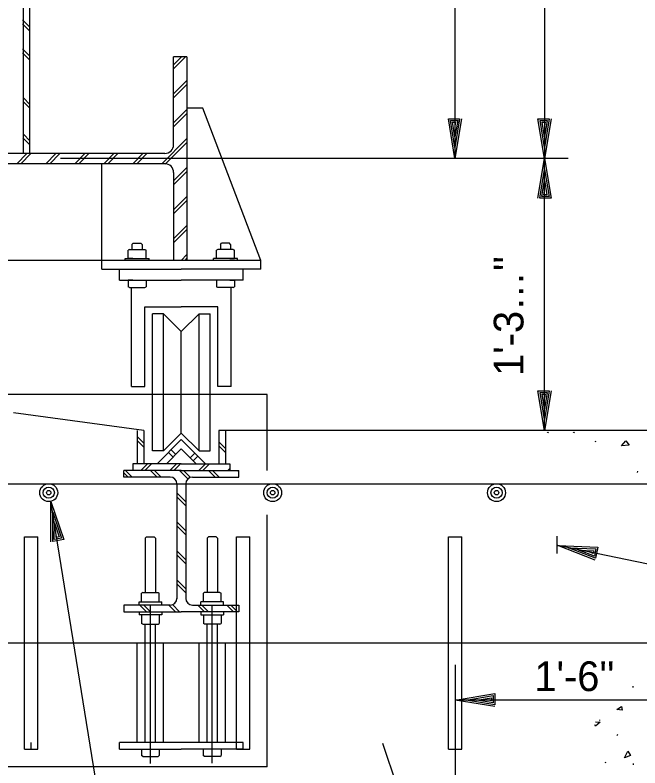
# Model space of a CAD drawing. Extents: x 0 to 320, y -4 to 473.
# Drawn here: x 29.538 to 32.485, y 15.085 to 18.631 of the extents above; entities that cross this region are included whole.
import ezdxf

# ---------------------------------------------------------------- set-up
doc = ezdxf.new("R2010")
doc.units = 0
for name, color, linetype in [('Level 10', 7, 'Continuous'), ('Level 2', 7, 'Continuous'), ('Level 25', 7, 'Continuous'), ('Level 3', 7, 'Continuous'), ('Level 44', 7, 'Continuous'), ('Level 50', 7, 'Continuous')]:
    doc.layers.add(name, color=color, linetype=linetype)

msp = doc.modelspace()

# ---------------------------------------------------------------- linework, layer by layer
at = {"layer": 'Level 10'}
for p, q in [((32.2744, 16.6204), (32.2772, 16.6259)), ((32.4725, 16.4769), (32.4743, 16.4832)), ((32.4522, 15.4636), (32.4522, 15.4694)), ((32.2959, 15.3076), (32.2955, 15.3122)), ((32.3775, 15.2381), (32.3803, 15.2436)), ((32.323, 15.107), (32.3222, 15.1117)), ((32.4544, 15.0996), (32.4544, 15.1059))]:
    msp.add_line(p, q, dxfattribs=at)
for points in [[(32.0532, 16.6662), (32.05, 16.6634), (32.0485, 16.6662)], [(32.1753, 16.6662), (32.1722, 16.6634), (32.1707, 16.6662)], [(32.2975, 15.3009), (32.2753, 15.2811), (32.2718, 15.2876)], [(32.2744, 15.3025), (32.2975, 15.3009)]]:
    msp.add_lwpolyline(points, dxfattribs=at)
for points in [[(32.3972, 16.6016), (32.4178, 16.6254), (32.4344, 16.6057)], [(32.4009, 15.3566), (32.3756, 15.3598), (32.3969, 15.3741)], [(32.4408, 15.1434), (32.4124, 15.1323), (32.4274, 15.1631)]]:
    msp.add_lwpolyline(points, close=True, dxfattribs=at)
at = {"layer": 'Level 2'}
for p, q in [((29.5776, 17.979), (29.5776, 22.1736)), ((29.6089, 17.979), (29.6089, 21.6319)), ((29.6053, 18.5767), (29.5741, 18.608)), ((29.6053, 18.5579), (29.5741, 18.5891)), ((29.6053, 18.44), (29.5741, 18.4713)), ((29.6053, 18.4212), (29.5741, 18.4524)), ((30.286, 18.0207), (30.286, 18.434)), ((30.3485, 18.434), (30.286, 18.434)), ((30.286, 18.3781), (30.3418, 18.434)), ((30.286, 18.397), (30.323, 18.434)), ((30.3485, 18.434), (30.3485, 17.4757)), ((30.286, 18.2603), (30.3485, 18.3228)), ((30.286, 18.2414), (30.3485, 18.3039)), ((29.6089, 18.2097), (29.5776, 18.2409)), ((29.6076, 18.1921), (29.5776, 18.2221)), ((30.4235, 18.1921), (30.3485, 18.1921)), ((30.6974, 17.4757), (30.4235, 18.1921)), ((30.286, 18.1236), (30.3485, 18.1861)), ((30.286, 18.1047), (30.3485, 18.1672)), ((29.6064, 18.0218), (29.5752, 18.0531)), ((29.6089, 18.0384), (29.5776, 18.0696)), ((30.2298, 17.9307), (30.3485, 18.0494)), ((30.2465, 17.9285), (30.3485, 18.0305)), ((30.2443, 17.979), (29.1558, 17.979)), ((29.5462, 17.9307), (29.5946, 17.979)), ((29.5651, 17.9307), (29.6134, 17.979)), ((29.6829, 17.9307), (29.7313, 17.979)), ((29.7018, 17.9307), (29.7501, 17.979)), ((32.146, 17.9548), (29.7529, 17.9548)), ((29.8197, 17.9307), (29.868, 17.979)), ((29.8385, 17.9307), (29.8868, 17.979)), ((29.9564, 17.9307), (30.0047, 17.979)), ((29.9752, 17.9307), (30.0236, 17.979)), ((30.0931, 17.9307), (30.1414, 17.979)), ((30.1119, 17.9307), (30.1603, 17.979)), ((30.2443, 17.9307), (29.1558, 17.9307)), ((29.9474, 17.4757), (29.9474, 17.9307)), ((30.286, 17.8502), (30.3485, 17.9127)), ((30.286, 17.8313), (30.3485, 17.8938)), ((30.286, 17.889), (30.286, 17.4757)), ((30.286, 17.7135), (30.3485, 17.776)), ((30.286, 17.6946), (30.3485, 17.7571)), ((30.286, 17.5768), (30.3485, 17.6393)), ((30.286, 17.5579), (30.3485, 17.6204)), ((30.0898, 17.5508), (30.0959, 17.5569)), ((30.0959, 17.5569), (30.1323, 17.5569)), ((30.1383, 17.5508), (30.1323, 17.5569)), ((30.5065, 17.5508), (30.5126, 17.5569)), ((30.5489, 17.5569), (30.5126, 17.5569)), ((30.555, 17.5508), (30.5489, 17.5569)), ((30.0778, 17.5274), (30.0722, 17.5242)), ((30.0722, 17.4844), (30.0722, 17.5242)), ((30.0778, 17.5274), (30.1503, 17.5274)), ((30.0898, 17.5508), (30.0898, 17.5274)), ((30.1383, 17.5508), (30.1383, 17.5274)), ((30.1503, 17.5274), (30.1559, 17.5242)), ((30.1559, 17.4844), (30.1559, 17.5242)), ((30.4945, 17.5274), (30.4889, 17.5242)), ((30.4889, 17.4844), (30.4889, 17.5242)), ((30.567, 17.5274), (30.4945, 17.5274)), ((30.5065, 17.5508), (30.5065, 17.5274)), ((30.555, 17.5508), (30.555, 17.5274)), ((30.567, 17.5274), (30.5726, 17.5242)), ((30.5726, 17.4844), (30.5726, 17.5242)), ((30.0574, 17.4844), (30.1708, 17.4844)), ((30.0574, 17.4757), (30.0574, 17.4844)), ((30.0722, 17.4844), (30.1559, 17.4844)), ((30.0934, 17.4844), (30.0722, 17.4844)), ((30.0898, 17.4829), (30.0898, 17.4844)), ((30.1383, 17.4829), (30.1383, 17.4844)), ((30.1708, 17.4757), (30.1708, 17.4844)), ((30.3216, 17.4757), (30.3485, 17.5025)), ((30.3404, 17.4757), (30.3485, 17.4837)), ((30.5874, 17.4844), (30.4741, 17.4844)), ((30.4741, 17.4757), (30.4741, 17.4844)), ((30.5726, 17.4844), (30.4889, 17.4844)), ((30.5065, 17.4829), (30.5065, 17.4844)), ((30.5514, 17.4844), (30.5726, 17.4844)), ((30.555, 17.4829), (30.555, 17.4844)), ((30.5874, 17.4757), (30.5874, 17.4844)), ((30.6974, 17.4757), (28.7443, 17.4757)), ((29.9474, 17.434), (29.9474, 17.4757)), ((30.6974, 17.434), (30.6974, 17.4757)), ((29.9474, 17.434), (30.3224, 17.434)), ((30.0308, 17.3819), (30.0308, 17.434)), ((30.6974, 17.434), (30.3224, 17.434)), ((30.6141, 17.3819), (30.6141, 17.434)), ((30.0308, 17.3819), (30.3224, 17.3819)), ((30.0724, 17.3818), (30.1562, 17.3818)), ((30.0936, 17.3818), (30.0724, 17.3818)), ((30.0724, 17.3818), (30.0724, 17.3511)), ((30.0901, 17.3833), (30.0901, 17.3818)), ((30.1386, 17.3833), (30.1386, 17.3818)), ((30.1562, 17.3818), (30.1562, 17.3511)), ((30.6141, 17.3819), (30.3224, 17.3819)), ((30.5724, 17.3818), (30.4886, 17.3818)), ((30.4886, 17.3818), (30.4886, 17.3511)), ((30.5063, 17.3833), (30.5063, 17.3818)), ((30.5512, 17.3818), (30.5724, 17.3818)), ((30.5548, 17.3833), (30.5548, 17.3818)), ((30.5724, 17.3818), (30.5724, 17.3511)), ((30.0781, 17.3478), (30.0724, 17.3511)), ((30.0781, 17.3478), (30.1506, 17.3478)), ((30.0878, 16.8819), (30.0878, 17.3478)), ((30.1506, 17.3478), (30.1562, 17.3511)), ((30.4943, 17.3478), (30.4886, 17.3511)), ((30.5668, 17.3478), (30.4943, 17.3478)), ((30.5571, 16.8819), (30.5571, 17.3478)), ((30.5668, 17.3478), (30.5724, 17.3511)), ((30.1503, 16.8819), (30.1503, 17.2569)), ((30.1503, 17.2569), (30.3224, 17.2569)), ((30.4946, 17.2569), (30.3224, 17.2569)), ((30.4946, 16.8819), (30.4946, 17.2569)), ((30.187, 16.5781), (30.187, 17.2239)), ((30.2391, 17.2239), (30.187, 17.2239)), ((30.2391, 16.5781), (30.2391, 17.2239)), ((30.2391, 17.2239), (30.3224, 17.1406)), ((30.4058, 17.2239), (30.3224, 17.1406)), ((30.4058, 16.5781), (30.4058, 17.2239)), ((30.4058, 17.2239), (30.4578, 17.2239)), ((30.4578, 16.5781), (30.4578, 17.2239)), ((30.3224, 16.6614), (30.3224, 17.1406)), ((30.3224, 16.6614), (30.3224, 17.1406)), ((30.0878, 16.8819), (30.1503, 16.8819)), ((30.5571, 16.8819), (30.4946, 16.8819)), ((30.7278, 16.8433), (29.3706, 16.8433)), ((30.7278, 16.4866), (30.7278, 16.8433)), ((30.1453, 16.6736), (29.5308, 16.7569)), ((30.1141, 16.6736), (30.1141, 16.5173)), ((30.1453, 16.6736), (30.1453, 16.5173)), ((30.4995, 16.6736), (30.4995, 16.5173)), ((32.5724, 16.6736), (30.4995, 16.6736)), ((30.5308, 16.6736), (30.5308, 16.5173)), ((30.1453, 16.6145), (30.1141, 16.6458)), ((30.3224, 16.6319), (30.2078, 16.5173)), ((30.3224, 16.6614), (30.2391, 16.5781)), ((30.3224, 16.6614), (30.4058, 16.5781)), ((30.3224, 16.6319), (30.437, 16.5173)), ((30.1453, 16.5957), (30.1141, 16.6269)), ((30.5308, 16.5899), (30.4995, 16.6211)), ((30.5308, 16.571), (30.4995, 16.6023)), ((30.2391, 16.5781), (30.187, 16.5781)), ((30.3224, 16.5877), (30.252, 16.5173)), ((30.2838, 16.5491), (30.2617, 16.5712)), ((30.2965, 16.5618), (30.2744, 16.5839)), ((30.3224, 16.5877), (30.3928, 16.5173)), ((30.3646, 16.5455), (30.3867, 16.5676)), ((30.4058, 16.5781), (30.4578, 16.5781)), ((30.3781, 16.532), (30.4002, 16.5541)), ((30.3224, 16.5173), (30.0933, 16.5173)), ((30.0933, 16.5173), (30.0933, 16.4861)), ((30.1316, 16.4861), (30.1629, 16.5173)), ((30.1505, 16.4861), (30.1817, 16.5173)), ((30.2683, 16.4861), (30.2996, 16.5173)), ((30.2872, 16.4861), (30.3184, 16.5173)), ((30.3224, 16.5173), (30.5516, 16.5173)), ((30.405, 16.4861), (30.4363, 16.5173)), ((30.4239, 16.4861), (30.4551, 16.5173)), ((30.5417, 16.4861), (30.5516, 16.4959)), ((30.5516, 16.5173), (30.5516, 16.4861)), ((30.3224, 16.4861), (30.0516, 16.4861)), ((30.0516, 16.4548), (30.0516, 16.4861)), ((30.0716, 16.4548), (30.0516, 16.4749)), ((30.2703, 16.4548), (30.0516, 16.4548)), ((30.0905, 16.4548), (30.0592, 16.4861)), ((30.2083, 16.4548), (30.1771, 16.4861)), ((30.2272, 16.4548), (30.1959, 16.4861)), ((30.3533, 16.4466), (30.3138, 16.4861)), ((30.3224, 16.4861), (30.5933, 16.4861)), ((30.3653, 16.4534), (30.3326, 16.4861)), ((30.3745, 16.4548), (30.5933, 16.4548)), ((30.4817, 16.4548), (30.4505, 16.4861)), ((30.5006, 16.4548), (30.4693, 16.4861)), ((30.5933, 16.48), (30.5872, 16.4861)), ((30.5933, 16.4548), (30.5933, 16.4861)), ((30.3016, 16.4236), (30.3016, 15.8809)), ((30.3433, 16.4236), (30.3433, 15.8809)), ((30.3433, 16.3388), (30.3016, 16.3804)), ((30.3433, 16.3199), (30.3016, 16.3616)), ((30.3433, 16.2021), (30.3016, 16.2437)), ((30.7278, 15.0896), (30.7278, 16.2765)), ((30.3433, 16.1832), (30.3016, 16.2249)), ((29.5828, 15.1736), (29.5828, 16.1736)), ((29.6453, 15.1736), (29.6453, 16.1736)), ((30.1522, 16.1675), (30.1583, 16.1736)), ((30.1583, 16.1736), (30.1946, 16.1736)), ((30.2007, 16.1675), (30.1946, 16.1736)), ((30.4441, 16.1675), (30.4502, 16.1736)), ((30.4866, 16.1736), (30.4502, 16.1736)), ((30.4926, 16.1675), (30.4866, 16.1736)), ((30.5828, 15.1736), (30.5828, 16.1736)), ((30.6453, 15.1736), (30.6453, 16.1736)), ((31.5828, 15.1736), (31.5828, 16.1736)), ((31.6453, 15.1736), (31.6453, 16.1736)), ((30.1523, 16.1675), (30.1523, 15.9107)), ((30.2008, 16.1675), (30.2008, 15.9107)), ((30.444, 16.1675), (30.444, 15.9107)), ((30.4925, 16.1675), (30.4925, 15.9107)), ((30.3433, 16.0654), (30.3016, 16.107)), ((30.3433, 16.0465), (30.3016, 16.0882)), ((30.3433, 15.9286), (30.3016, 15.9703)), ((30.3433, 15.9098), (30.3016, 15.9515)), ((30.1403, 15.9107), (30.1347, 15.9075)), ((30.1347, 15.8677), (30.1347, 15.9075)), ((30.1403, 15.9107), (30.2128, 15.9107)), ((30.2128, 15.9107), (30.2184, 15.9075)), ((30.2184, 15.8677), (30.2184, 15.9075)), ((30.432, 15.9107), (30.4264, 15.9075)), ((30.4264, 15.8677), (30.4264, 15.9075)), ((30.5045, 15.9107), (30.432, 15.9107)), ((30.5045, 15.9107), (30.5101, 15.9075)), ((30.5101, 15.8677), (30.5101, 15.9075)), ((30.2703, 15.8521), (30.0516, 15.8521)), ((30.0516, 15.8521), (30.0516, 15.8209)), ((30.1231, 15.8677), (30.2301, 15.8677)), ((30.1231, 15.8521), (30.1231, 15.8677)), ((30.1588, 15.8209), (30.1275, 15.8521)), ((30.1776, 15.8209), (30.1464, 15.8521)), ((30.1523, 15.8662), (30.1523, 15.8677)), ((30.2008, 15.8662), (30.2008, 15.8677)), ((30.2301, 15.8521), (30.2301, 15.8677)), ((30.2955, 15.8209), (30.2642, 15.8521)), ((30.3143, 15.8209), (30.2811, 15.8541)), ((30.3745, 15.8521), (30.5933, 15.8521)), ((30.4322, 15.8209), (30.4009, 15.8521)), ((30.5218, 15.8677), (30.4147, 15.8677)), ((30.4147, 15.8521), (30.4147, 15.8677)), ((30.451, 15.8209), (30.4198, 15.8521)), ((30.444, 15.8662), (30.444, 15.8677)), ((30.4925, 15.8662), (30.4925, 15.8677)), ((30.5218, 15.8521), (30.5218, 15.8677)), ((30.5689, 15.8209), (30.5376, 15.8521)), ((30.5877, 15.8209), (30.5565, 15.8521)), ((30.5933, 15.8521), (30.5933, 15.8209)), ((30.0516, 15.8209), (30.3224, 15.8209)), ((30.1231, 15.8209), (30.1231, 15.8053)), ((30.1766, 15.1059), (30.1766, 15.8496)), ((30.2301, 15.8209), (30.2301, 15.8053)), ((30.5933, 15.8209), (30.3224, 15.8209)), ((30.4147, 15.8209), (30.4147, 15.8053)), ((30.4683, 15.1073), (30.4683, 15.8496)), ((30.5218, 15.8209), (30.5218, 15.8053)), ((30.2301, 15.8053), (30.1231, 15.8053)), ((30.1347, 15.8053), (30.1347, 15.7655)), ((30.1523, 15.8068), (30.1523, 15.8053)), ((30.2008, 15.8068), (30.2008, 15.8053)), ((30.2184, 15.8053), (30.2184, 15.7655)), ((30.4147, 15.8053), (30.5218, 15.8053)), ((30.4264, 15.8053), (30.4264, 15.7655)), ((30.444, 15.8068), (30.444, 15.8053)), ((30.4925, 15.8068), (30.4925, 15.8053)), ((30.5101, 15.8053), (30.5101, 15.7655)), ((30.1403, 15.7623), (30.1347, 15.7655)), ((30.1403, 15.7623), (30.2128, 15.7623)), ((30.1523, 15.2048), (30.1523, 15.7623)), ((30.2008, 15.2048), (30.2008, 15.7623)), ((30.2128, 15.7623), (30.2184, 15.7655)), ((30.432, 15.7623), (30.4264, 15.7655)), ((30.5045, 15.7623), (30.432, 15.7623)), ((30.444, 15.2048), (30.444, 15.7623)), ((30.4925, 15.2048), (30.4925, 15.7623)), ((30.5045, 15.7623), (30.5101, 15.7655)), ((23.1141, 15.6736), (33.1141, 15.6736)), ((30.1141, 15.2048), (30.1141, 15.6736)), ((30.2391, 15.2048), (30.2391, 15.6736)), ((30.4058, 15.2048), (30.4058, 15.6736)), ((30.5308, 15.2048), (30.5308, 15.6736)), ((31.6141, 15.5702), (31.6141, 11.2486)), ((29.6141, 15.1736), (29.6141, 15.2048)), ((30.0308, 15.1736), (30.0308, 15.2048)), ((30.3224, 15.2048), (30.0308, 15.2048)), ((30.6141, 15.2048), (30.3224, 15.2048)), ((30.6141, 15.1736), (30.6141, 15.2048)), ((30.0308, 15.1736), (30.3224, 15.1736)), ((30.1349, 15.1734), (30.1349, 15.1428)), ((30.1406, 15.1395), (30.1349, 15.1428)), ((30.1526, 15.175), (30.1526, 15.1734)), ((30.2011, 15.175), (30.2011, 15.1734)), ((30.2131, 15.1395), (30.2187, 15.1428)), ((30.2187, 15.1734), (30.2187, 15.1428)), ((30.6141, 15.1736), (30.3224, 15.1736)), ((30.4261, 15.1734), (30.4261, 15.1428)), ((30.4318, 15.1395), (30.4261, 15.1428)), ((30.4438, 15.175), (30.4438, 15.1734)), ((30.4923, 15.175), (30.4923, 15.1734)), ((30.5043, 15.1395), (30.5099, 15.1428)), ((30.5099, 15.1734), (30.5099, 15.1428)), ((30.1406, 15.1395), (30.2131, 15.1395)), ((30.5043, 15.1395), (30.4318, 15.1395)), ((30.7278, 15.0896), (26.8833, 15.0896))]:
    msp.add_line(p, q, dxfattribs=at)
for centre, radius, start, end in [((30.2443, 18.0207), 0.0417, 270, 360), ((30.2443, 17.889), 0.0417, 0, 90), ((30.2703, 16.4236), 0.0313, 0, 90), ((30.3745, 16.4236), 0.0313, 90, 180), ((30.2703, 15.8834), 0.0313, 270, 360), ((30.3745, 15.8834), 0.0313, 180, 270)]:
    msp.add_arc(centre, radius, start, end, dxfattribs=at)
at = {"layer": 'Level 25'}
msp.add_line((31.2715, 15.2012), (32.3872, 11.8543), dxfattribs=at)
at = {"layer": 'Level 3'}
for p, q in [((32.0349, 21.8819), (32.0349, 17.9548)), ((31.6126, 19.9184), (31.6126, 17.9548)), ((32.0349, 16.6736), (32.0349, 17.9548)), ((23.4266, 16.4236), (32.8016, 16.4236)), ((29.708, 16.3402), (29.708, 16.3402)), ((29.7163, 16.2888), (29.7163, 16.2888)), ((33.1141, 15.4047), (31.6141, 15.4047))]:
    msp.add_line(p, q, dxfattribs=at)
for points in [[(29.7072, 16.1506), (29.708, 16.3402), (29.7684, 16.1605), (29.7161, 16.152), (29.7163, 16.2888), (29.7573, 16.1668), (29.7237, 16.1614), (29.7243, 16.2395), (29.7461, 16.1731), (29.7323, 16.1709), (29.7325, 16.1881)], [(30.0214, 13.3531), (30.1901, 13.3531), (29.708, 16.3402)], [(32.0945, 16.0951), (32.0945, 16.1764)], [(33.3434, 15.9016), (33.2155, 15.9016), (32.0969, 16.1319)]]:
    msp.add_lwpolyline(points, dxfattribs=at)
at = {"layer": 'Level 44'}
for p, q in [((29.5828, 16.1736), (29.6453, 16.1736)), ((30.5828, 16.1736), (30.6453, 16.1736)), ((31.5828, 16.1736), (31.6453, 16.1736)), ((29.5828, 15.1736), (29.6453, 15.1736)), ((30.5828, 15.1736), (30.6453, 15.1736)), ((31.5828, 15.1736), (31.6453, 15.1736))]:
    msp.add_line(p, q, dxfattribs=at)
at = {"layer": 'Level 50'}
for p, q in [((31.6126, 18.0068), (31.6126, 18.0068)), ((32.0349, 18.0068), (32.0349, 18.0068)), ((31.6126, 17.9548), (31.6126, 17.9548)), ((32.0349, 17.9548), (32.0349, 17.9548)), ((32.0349, 17.9548), (32.0349, 17.9548)), ((32.0349, 17.9028), (32.0349, 17.9028)), ((32.0349, 16.7256), (32.0349, 16.7256)), ((32.0349, 16.6736), (32.0349, 16.6736)), ((32.0969, 16.1319), (32.0969, 16.1319)), ((32.1478, 16.1214), (32.1478, 16.1214)), ((31.6141, 15.4047), (31.6141, 15.4047)), ((31.6661, 15.4047), (31.6661, 15.4047))]:
    msp.add_line(p, q, dxfattribs=at)
for points in [[(31.6436, 18.1418), (31.6126, 17.9548), (31.5816, 18.1418), (31.6346, 18.1418), (31.6126, 18.0068), (31.5916, 18.1338), (31.6256, 18.1338), (31.6126, 18.0568), (31.6016, 18.1258), (31.6156, 18.1258), (31.6126, 18.1088)], [(32.0659, 18.1418), (32.0349, 17.9548), (32.0039, 18.1418), (32.0569, 18.1418), (32.0349, 18.0068), (32.0139, 18.1338), (32.0479, 18.1338), (32.0349, 18.0568), (32.0239, 18.1258), (32.0379, 18.1258), (32.0349, 18.1088)], [(32.0039, 17.7678), (32.0349, 17.9548), (32.0659, 17.7678), (32.0129, 17.7678), (32.0349, 17.9028), (32.0559, 17.7758), (32.0219, 17.7758), (32.0349, 17.8528), (32.0459, 17.7838), (32.0319, 17.7838), (32.0349, 17.8008)], [(32.0659, 16.8606), (32.0349, 16.6736), (32.0039, 16.8606), (32.0569, 16.8606), (32.0349, 16.7256), (32.0139, 16.8526), (32.0479, 16.8526), (32.0349, 16.7756), (32.0239, 16.8446), (32.0379, 16.8446), (32.0349, 16.8276)], [(32.2738, 16.0638), (32.0969, 16.1319), (32.2863, 16.1246), (32.2756, 16.0726), (32.1478, 16.1214), (32.2764, 16.1164), (32.2696, 16.0831), (32.1968, 16.1113), (32.2666, 16.1082), (32.2638, 16.0945), (32.2477, 16.1008)], [(31.8011, 15.3737), (31.6141, 15.4047), (31.8011, 15.4357), (31.8011, 15.3827), (31.6661, 15.4047), (31.7931, 15.4257), (31.7931, 15.3917), (31.7161, 15.4047), (31.7851, 15.4157), (31.7851, 15.4017), (31.7681, 15.4047)]]:
    msp.add_lwpolyline(points, dxfattribs=at)
for centre, radius in [((29.6974, 16.3814), 0.0422), ((30.753, 16.3814), 0.0422), ((31.8085, 16.3814), 0.0422), ((29.6974, 16.3814), 0.0264), ((29.6974, 16.3814), 0.0105), ((30.753, 16.3814), 0.0264), ((30.753, 16.3814), 0.0105), ((31.8085, 16.3814), 0.0264), ((31.8085, 16.3814), 0.0105)]:
    msp.add_circle(centre, radius, dxfattribs=at)

# ---------------------------------------------------------------- texts
at = {"layer": 'Level 3'}
msp.add_text("1'-3…'' ", height=0.14, rotation=90, dxfattribs=at).set_placement((31.9354, 16.9311))
msp.add_text("1'-6''", height=0.14, dxfattribs=at).set_placement((31.987, 15.4468))

doc.saveas('drawing.dxf')
